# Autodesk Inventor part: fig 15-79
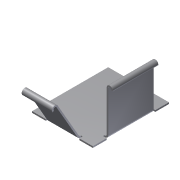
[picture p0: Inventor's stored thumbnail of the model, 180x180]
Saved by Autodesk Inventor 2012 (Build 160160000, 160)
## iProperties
Shininess: 77.0
Angle Display Precision: 2
Document Length Units: 11269
Document Angle Units: 11279
Document Time Units: 11290
Document Mass Units: 11283
Document Length Units Precision: 3
Document Angle Units Precision: 2
Compacted: True
Created: 2002-04
Part Number: fig 15-79
Document SubType Name: Sheet Metal
Density: 1 g/cm^3
Sheet Metal Rule: Default
Material: Default
Density: 0.0
Volumn: 0.0
Area: 0.0
PropertySet Name: Model Information
Control State: 0
Master: False
Checked Out: False
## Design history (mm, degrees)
node "Face1"
  sketch "Sketch1"
    geometry: L1 (-17.882, 11.882)-(2.118, 11.882); L2 (2.118, 11.882)-(2.118, -13.176); L3 (2.118, -13.176)-(-17.882, -13.176); L4 (-17.882, -13.176)-(-17.882, 11.882)
    constraints: 8 end point, 2 parallel, 1 horizontal, 1 perpendicular
    dimensions: "d17" = 20 distance of L2.end L3.end
node "Flange2"
node "Flange3"
feature "Hem8" dims "d82" = 0.5 (= BendReliefWidth), "d83" = 0.25 (= BendReliefDepth), "d84" = 1 (= MinimumRemnant), "d85" = 0.5 (= BendRadius), "d102" = 190 deg, "d103" = 0.5 (= BendRadius), "d104" = 0.5 (= d103), "SeamGap" = 0.01, "Thickness" = 0.5
feature "Hem9" dims "d89" = 0.5 (= BendReliefWidth), "d90" = 0.25 (= BendReliefDepth), "d91" = 1 (= MinimumRemnant), "d92" = 0.5 (= BendRadius), "d105" = 190 deg, "d106" = 0.5 (= BendRadius), "d107" = 0.5 (= d106), "SeamGap" = 0.01, "Thickness" = 0.5
body "Solid1"
face "Plate1" dims "Thickness" = 0.5
sketch "Sketch3"
  geometry: L1 (5, 0)-(20, 0); L2 (20, 0)-(20, 15); L3 (20, 15)-(5, 15); L4 (5, 15)-(5, 0)
  constraints: 8 end point
face "Plate3" dims "d6" = 15, "d7" = 90 deg, "d8" = 0.5 (= BendRadius), "d18" = 5, "d19" = 15, "Thickness" = 0.5, "MinimumRemnant" = 1 (= 2 x Thickness), "BendReliefWidth" = 0.5 (= Thickness)
bend "Bend2" dims "d6" = 15, "d7" = 90 deg, "d8" = 0.5 (= BendRadius), "d56" = 0.5 (= BendReliefWidth), "d57" = 0.25 (= BendReliefDepth), "d58" = 1 (= MinimumRemnant), "SeamGap" = 0.01, "Thickness" = 0.5, "MinimumRemnant" = 1 (= 2 x Thickness), "BendReliefWidth" = 0.5 (= Thickness), "TransitionRadius" = 0.5 (= BendRadius)
sketch "Sketch6"
  geometry: L1 (15, 0)-(5, 0); L2 (5, 0)-(5, 15); L3 (5, 15)-(15, 15); L4 (15, 15)-(15, 0)
  constraints: 8 end point
face "Plate4" dims "d20" = 5, "d21" = 10, "d23" = 15, "d24" = 60 deg, "d25" = 0.5 (= BendRadius), "Thickness" = 0.5, "MinimumRemnant" = 1 (= 2 x Thickness), "BendReliefWidth" = 0.5 (= Thickness)
bend "Bend3" dims "d22" = 0.5 (= BendRadius), "d23" = 15, "d24" = 60 deg, "d25" = 0.5 (= BendRadius), "d59" = 0.5 (= BendReliefWidth), "d60" = 0.25 (= BendReliefDepth), "d61" = 1 (= MinimumRemnant), "SeamGap" = 0.01, "Thickness" = 0.5, "MinimumRemnant" = 1 (= 2 x Thickness), "BendReliefWidth" = 0.5 (= Thickness)
sketch "Sketch12"
  geometry: L1 (0.433, 0.25)-(0, 0); L2 (-0.816, -0.571)-(-1.199, -0.893); A1 r 0.5 centre (-0.433, -0.25) between (0, 0) and (-0.816, -0.571); A2 r 1 centre (-0.433, -0.25) between (0.433, 0.25) and (-1.199, -0.893); 2 further points
  constraints: 4 end point, 4 point on circle
sketch "Sketch13"
  geometry: L1 (0.5, 0)-(0, 0); L2 (-0.992, -0.087)-(-1.485, -0.174); A1 r 0.5 centre (-0.5, 0) between (0, 0) and (-0.992, -0.087); A2 r 1 centre (-0.5, 0) between (0.5, 0) and (-1.485, -0.174); 2 further points
  constraints: 4 end point, 4 point on circle
other parameters: "BendRadius" = 0.5 (= Thickness), "BendReliefDepth" = 0.25 (= 0.5 x Thickness), "CornerReliefSize" = 2 (= 4 x Thickness), "d0" = 0.5 (= BendRadius), "d5" = 0.5 (= BendRadius), "d26" = 0.5 (= BendRadius), "d30" = 0.5 (= BendRadius), "JacobiRadiusSize" = 0.5 (= Thickness), "GapSize" = 0.5 (= Thickness)
